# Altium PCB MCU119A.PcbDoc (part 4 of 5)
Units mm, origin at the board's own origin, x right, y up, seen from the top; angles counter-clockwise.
Board outline 58.62 x 144.37 mm, 6 copper layers (Top Signal, GND, Middle Signal, PWR, GND2, Bottom Signal), stack 1.566 mm thick; 316 components, 238 nets, 1210 pads, 1064 vias.
Unrouted connection lines stored in the file: 59.
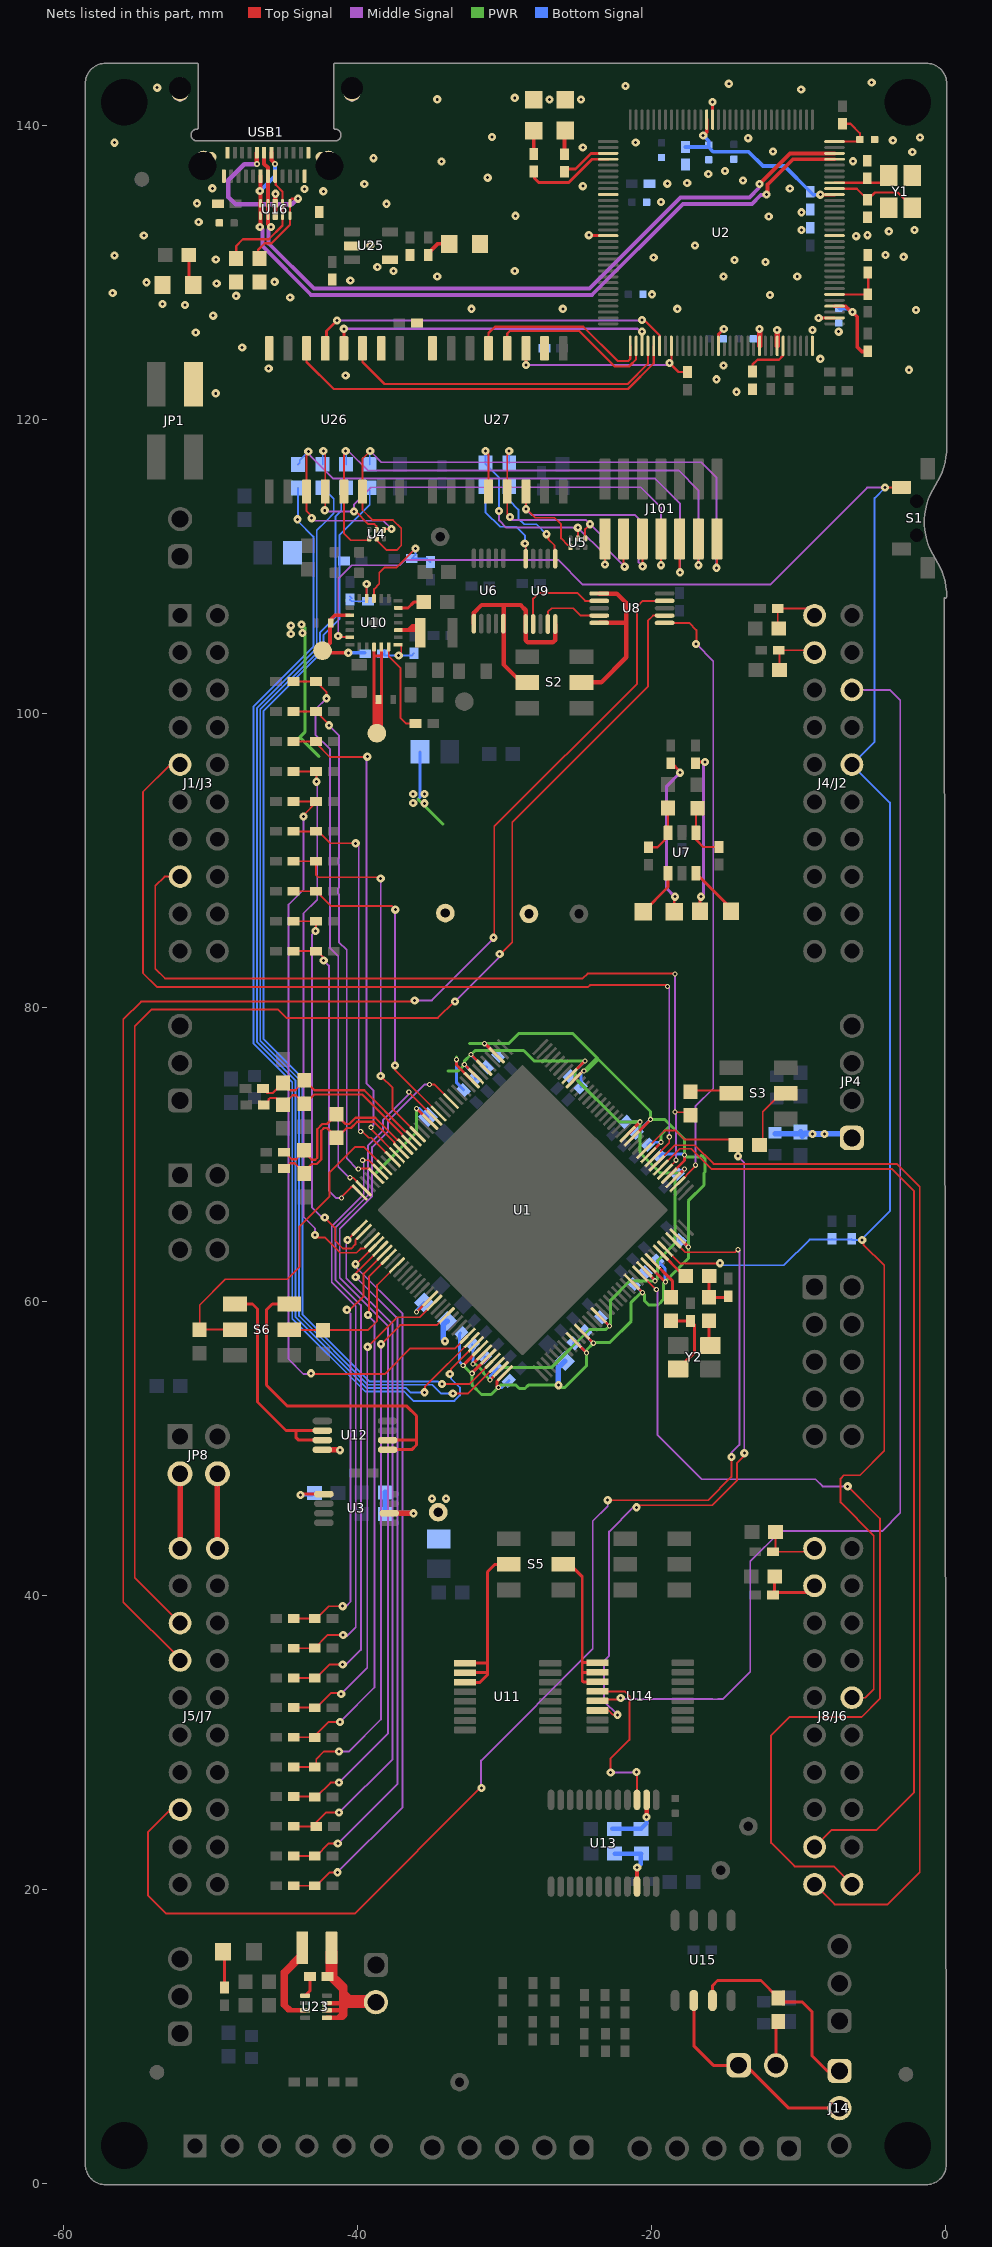
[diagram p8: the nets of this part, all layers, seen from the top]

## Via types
v1: diameter 0.559, hole 0.203, Top Signal to Bottom Signal, tented both sides, 833 vias
v2: diameter 0.5, hole 0.2, Top Signal to Bottom Signal, tented both sides, 146 vias
v3: diameter 0.356, hole 0.203, Top Signal to Bottom Signal, tented both sides, 83 vias
v4: diameter 0.4, hole 0.2, Top Signal to Bottom Signal, tented both sides, 2 vias

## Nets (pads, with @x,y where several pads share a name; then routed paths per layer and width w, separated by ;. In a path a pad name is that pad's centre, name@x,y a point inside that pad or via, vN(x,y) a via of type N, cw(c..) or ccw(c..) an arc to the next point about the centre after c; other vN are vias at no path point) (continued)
GPIO70_BP: J5/J7.44 U8.9 | length 101.4
  Top Signal w0.127: J5/J7.44@-52.061,35.58 -52.061,35.678 -55.931,39.548 -55.931,79.197 -54.712,80.416 -36.17,80.416 v1(-36.093,80.493) ; v1(-30.734,84.76) -30.734,84.942 -30.683,84.993 -30.683,92.329 -20.955,102.057 -20.955,107.29 -20.562,107.683 U8.9@-19.086,107.683
  Middle Signal w0.127: v1(-36.093,80.493) -34.927,80.493 -30.734,84.685 v1(-30.734,84.76)
GPIO70_UARTTX: U8.2 U9.2 | length 6.6
  Top Signal w0.127: U9.2@-28.034,106.106 -28.034,107.145 -28.034,107.831 -27.637,108.228 -25.039,108.228 -24.494,107.683 U8.2@-23.536,107.683
GPIO71: U1.111 U8.6 | length 41.6
  Top Signal w0.127: U8.6@-19.086,106.183 -17.41,106.183 -16.92,105.693 -16.92,104.771 v1(-16.942,104.75) ; U1.111@-18.208,67.989 -16.993,69.204 v3(-16.993,69.28)
  Middle Signal w0.127: v3(-16.993,69.28) -16.993,73.279 -15.773,74.498 -15.773,103.581 v1(-16.942,104.75)
GPIO71_BP: J5/J7.43 U8.7 | length 97.5
  Top Signal w0.127: J5/J7.43@-52.061,38.12 -55.143,41.202 -55.143,78.74 -54,79.883 -45.415,79.883 -44.831,79.299 -34.519,79.299 -33.401,80.416 v1(-33.36,80.416) ; v1(-30.312,83.642) -30.277,83.642 -29.457,84.462 -29.457,92.615 -20.226,101.846 -20.226,106.335 -19.878,106.683 U8.7@-19.086,106.683
  Middle Signal w0.127: v1(-33.36,80.416) -30.312,83.464 v1(-30.312,83.642)
GPIO71_UARTRX: U8.4 U9.4 | length 4.6
  Top Signal w0.127: U9.4@-27.034,106.106 -27.034,106.926 -26.777,107.183 -25.293,107.183 -24.793,106.683 U8.4@-23.536,106.683
GPIO72: J1/J3.8 R31.1 U1.114 | length 58.2
  Top Signal w0.127: J1/J3.8@-52.061,88.92 -53.117,88.92 -53.746,88.29 -53.746,82.652 -53.086,81.991 -24.663,81.991 -24.333,82.321 v3@-18.39,82.321 ; U1.114@-19.056,68.838 -18.313,69.581 v3(-18.313,69.621) ; v3(-18.39,72.907) -18.362,72.88 R31.1@-17.323,72.88
  Middle Signal w0.127: v3(-18.39,82.296) v3(-18.39,72.907) -18.313,72.831 v3(-18.313,69.621)
GPIO76: J8/J6.72 U1.115 | length 68.2
  Top Signal w0.127: U1.115@-19.339,69.121 -18.059,70.401 -17.264,70.401 -15.875,69.012 -3.607,69.012 -2.108,67.513 -2.108,26.594 -4.674,24.028 -7.732,24.028 J8/J6.72@-8.881,22.88
GPIO77: J8/J6.71 U1.116 | length 75
  Top Signal w0.127: U1.116@-19.622,69.403 -18.388,70.637 -17.026,70.637 -15.756,69.367 -3.277,69.367 -1.727,67.818 -1.727,21.158 -3.912,18.974 -7.515,18.974 J8/J6.71@-8.881,20.34 J8/J6.71@-9.072,20.34
GPIO78: J1/J3.5 U1.117 | length 64.1
  Top Signal w0.127: J1/J3.5@-52.061,96.54 -52.736,96.54 -54.585,94.691 -54.585,82.347 -53.645,81.407 -24.285,81.407 -24.158,81.534 -18.999,81.534 v3(-18.898,81.432) ; U1.117@-19.905,69.686 -18.771,70.82 v3(-18.771,71.213)
  Middle Signal w0.127: v3(-18.898,81.432) -18.771,81.305 v3(-18.771,71.213)
GPIO84: R33.2 U1.119 U14.14 | length 54.7
  Top Signal w0.127: U14.14@-23.652,32.172 -22.906,32.172 -22.614,31.879 v1(-22.291,31.879) ; v1(-21.006,45.999) -20.87,46.135 -15.841,46.135 -14.173,47.803 -14.173,48.997 -13.665,49.505 v1(-13.665,49.682) ; U1.119@-20.47,70.252 -19.094,71.628 -18.339,71.628 -17.729,71.018 -14.606,71.018 R33.2@-14.237,70.649 ; v1(-14.097,69.89) R33.2@-14.097,70.333
  Middle Signal w0.127: v1(-22.291,31.879) -23.216,32.804 -23.216,35.535 -22.86,35.89 -22.86,44.348 -21.209,45.999 v1(-21.006,45.999) ; v1(-14.097,69.89) -13.665,69.459 v1(-13.665,49.682)
GPIO84_BP: J4/J2.18 U14.13 | length 89.3
  Top Signal w0.127: U14.13@-23.652,32.822 -23.555,32.918 -22.18,32.918 v1(-22.073,33.025)
  Middle Signal w0.127: v1(-22.073,33.025) -21.991,32.943 -15.831,32.943 -15.827,32.939 -15.465,32.939 -15.461,32.943 -15.119,32.943 -13.259,34.803 -13.259,42.316 -11.201,44.374 -4.293,44.374 -3.048,45.618 -3.048,100.914 -3.754,101.62 J4/J2.18@-6.341,101.62
GPIO84_Q1A: U13.3 U14.12 | length 11.7
  Top Signal w0.127: U14.12@-23.652,33.472 -21.813,33.472 -21.488,33.147 -21.488,30.175 -22.758,28.905 v1(-22.758,27.96) ; U13.3@-20.966,26.089 v1@-20.966,27.991
  Middle Signal w0.127: v1(-22.758,27.96) -21.037,27.96 v1(-21.006,27.991)
GPIO103: J5/J7.48 U1.105 | length 86.6
  Top Signal w0.127: J5/J7.48@-52.061,25.42 -52.722,25.42 -54.254,23.887 -54.254,19.583 -53.035,18.364 -40.154,18.364 -31.619,26.899 v1(-31.547,26.899) ; v1(-22.962,46.482) -16.124,46.482 -14.541,48.065 v1(-14.541,49.428) ; U1.105@-18.49,64.171 -17.675,63.355 -14.273,63.355 v3(-14.097,63.531)
  Middle Signal w0.127: v1@-31.572,26.899 -31.572,28.766 -23.978,36.36 -23.978,45.067 -22.962,46.083 v1(-22.962,46.482) ; v1(-14.541,49.428) -14.541,49.695 -13.995,50.241 -13.995,63.429 v3(-14.097,63.531)
GPIO127: J8/J6.51 U1.97 | length 63.6
  Top Signal w0.127: U1.97@-20.753,61.908 -19.656,60.811 v3(-19.65,60.811) ; v1(-6.629,47.426) -4.441,45.237 -4.441,32.973 -5.69,31.725 -10.592,31.725 -11.836,30.48 -11.836,23.165 -10.236,21.565 -7.566,21.565 J8/J6.51@-6.341,20.34
  Middle Signal w0.127: v3(-19.65,60.811) -19.583,60.744 -19.583,50.927 -16.561,47.904 -8.819,47.904 -8.341,47.426 v1(-6.629,47.426)
GPIO220_X1: R21.1 U1.102 | length 2.4
  Top Signal w0.203: U1.102@-19.339,63.322 -17.866,61.849 R21.1@-17.539,61.849
GPIO221_X2: R20.1 U1.100 | length 3.1
  Top Signal w0.203: U1.100@-19.905,62.757 -18.561,61.413 -18.561,60.395 R20.1@-18.665,60.291 ; R20.1@-18.491,60.515 R20.1@-18.455,60.479
MCU_A0/DACA_OUT: C39.1 R37.2 U1.36 | length 21
  Top Signal w0.127: R37.2@-44.334,83.844 -42.927,83.844 C39.1@-42.806,83.844 -42.738,83.844 -42.285,83.391 v1(-42.285,83.21) ; v3(-41.072,67.038) -41.072,67.138 -40.422,67.788 -40.254,67.788 -39.89,67.424 U1.36@-39.845,67.424
  Middle Signal w0.127: v1(-42.285,83.21) -41.935,82.86 -41.935,67.551 -41.422,67.038 v3(-41.072,67.038)
MCU_A1: C26.1 R38.2 U1.35 | length 38.1
  Top Signal w0.127: R38.2@-44.334,102.191 C26.1@-42.806,102.191 -42.088,101.473 v1(-42.088,101.051) ; v3(-40.493,68.428) -40.284,68.428 U1.35@-39.562,67.706
  Middle Signal w0.127: v1(-42.088,101.051) -42.85,100.289 -42.85,98.577 -41.848,97.576 -41.848,84.866 -41.848,84.504 -41.848,84.051 -41.783,83.985 -41.783,83.976 -41.295,83.489 -41.295,69.179 -40.544,68.428 v3(-40.493,68.428)
MCU_A2: C40.1 R39.2 U1.28 | length 27.3
  Top Signal w0.127: R39.2@-44.334,91.998 C40.1@-42.806,91.998 -42.745,91.938 -42.679,91.872 -42.536,91.872 -41.85,91.186 v1(-40.112,91.186) ; v3(-39.767,71.577) -39.726,71.594 ccw(c-39.646,71.675) -39.646,71.561 -39.234,71.149 -39.048,71.149 U1.28@-37.585,69.686
  Middle Signal w0.127: v1(-40.112,91.186) -39.903,90.978 -39.903,71.907 -39.903,71.713 v3(-39.767,71.577)
MCU_A3: C27.1 R40.2 U1.27 | length 33.7
  Top Signal w0.127: R40.2@-44.334,98.114 C27.1@-42.806,98.114 -42.806,98 -41.859,97.053 -39.345,97.053 v1(-39.319,97.079) ; v3(-39.065,71.857) -39.065,71.735 U1.27@-37.3,69.969
  Middle Signal w0.127: v1(-39.319,97.079) -39.37,97.028 -39.37,74.828 -38.887,74.346 -38.887,72.034 v3(-39.065,71.857)
MCU_A4A5_N: C24.1 C29.2 R42.2 U1.23 | length 12.8
  Top Signal w0.152: R42.2@-46.415,74.495 -46.114,74.193 -45.745,74.193 -45.072,74.867 C29.2@-45.069,74.867 -44.574,74.371 -44.221,74.371 -43.612,74.981 C24.1@-43.612,75.07 -43.567,75.025 -42.913,74.371 -39.522,74.371 -36.728,71.577 -36.645,71.577 U1.23@-36.168,71.1
MCU_A4A5_P: C24.2 C41.2 R41.2 U1.24 | length 12.5
  Top Signal w0.152: R41.2@-46.365,73.368 -46.025,73.708 -46.025,73.762 -45.928,73.858 -45.55,73.858 -45.06,73.368 -44.386,74.041 -44.183,74.041 C24.2@-43.612,73.47 -43.548,73.47 -42.926,74.092 -39.656,74.092 -36.957,71.393 -36.957,71.324 U1.24@-36.451,70.818
MCU_A6: C42.1 R43.2 U1.18 | length 48.6
  Top Signal w0.127: R43.2@-44.323,34.389 -44.318,34.384 -42.795,34.384 -41.872,35.306 v1(-40.996,35.306) ; v3(-36.497,74.261) -36.497,74.257 U1.18@-34.754,72.515
  Middle Signal w0.127: v1(-40.996,35.306) -40.742,35.306 -39.751,36.297 -39.751,59.757 -41.49,61.496 -41.49,65.007 -39.279,67.217 -39.279,70.597 -38.259,71.618 -38.259,72.342 -36.497,74.104 v3(-36.497,74.261)
MCU_A7: C30.1 R45.2 U1.17 | length 22.5
  Top Signal w0.127: R45.2@-44.334,87.921 C30.1@-42.806,87.921 -41.803,86.919 -37.668,86.919 v1(-37.414,86.665) ; v1(-37.44,76.073) -37.44,75.766 U1.17@-34.471,72.798
  Middle Signal w0.127: v1(-37.44,76.073) -37.44,86.639 v1(-37.414,86.665)
MCU_A14/B14/C14: C43.1 R46.2 U1.32 | length 35.4
  Top Signal w0.127: R46.2@-44.334,100.152 C43.1@-42.806,100.152 -41.935,99.282 v1(-41.935,99.212) ; v3(-39.929,69.012) -39.878,69.063 -39.221,69.063 U1.32@-38.714,68.555
  Middle Signal w0.127: v1(-41.935,99.212) -41.25,98.527 -41.25,90.184 -41.286,90.148 -41.286,89.786 -41.25,89.749 -41.25,88.172 -41.305,88.116 -41.305,87.754 -41.25,87.698 -41.25,84.464 -40.716,83.931 -40.716,69.736 -39.992,69.012 v3(-39.929,69.012)
MCU_A15/B15/C15: C31.1 R47.2 U1.31 | length 39.7
  Top Signal w0.127: R47.2@-44.323,36.41 C31.1@-42.937,36.41 ; C31.1@-42.891,36.424 -42.002,37.313 v1(-40.957,37.313) ; v3(-39.637,69.616) -39.209,69.616 U1.31@-38.431,68.838
  Middle Signal w0.127: v1(-40.957,37.313) -40.881,37.236 -40.716,37.236 -40.107,37.846 -40.107,59.665 -41.741,61.299 -41.741,65.117 -39.562,67.296 -39.562,69.541 v3(-39.637,69.616)
MCU_B2B3_N: C25.1 C32.2 R49.2 U1.25 | length 12.7
  Top Signal w0.152: R49.2@-44.993,70.155 -44.936,70.155 -44.468,69.686 -44.157,69.686 -43.637,70.206 C32.2@-43.637,70.295 ; C32.2@-43.637,70.18 -43.104,69.647 -42.87,69.647 -42.731,69.785 -42.731,71.734 -42.38,72.085 -42.066,72.085 C25.1@-41.402,72.749 -41.402,72.683 -40.805,72.085 -40.553,72.085 -40.126,72.511 -38.771,72.511 -37.278,71.018 -37.217,71.018 U1.25@-36.734,70.535
MCU_B2B3_P: C25.2 C44.2 R48.2 U1.26 | length 12.5
  Top Signal w0.152: R48.2@-44.993,69.063 -44.907,69.063 -44.566,69.403 -44.257,69.403 C44.2@-43.612,68.758 ; C44.2@-43.612,68.718 C44.2@-43.612,68.758 ; U1.26@-37.017,70.252 -37.49,70.726 -37.49,70.835 -38.887,72.232 -40.011,72.232 -40.437,71.806 -40.727,71.806 -41.384,71.149 C25.2@-41.402,71.149 -42.059,71.806 -42.264,71.806 -42.452,71.618 -42.452,69.67 -42.754,69.367 -43.093,69.367 -43.612,68.849 C44.2@-43.612,68.758
MCU_B9: C33.1 R51.2 U1.14 | length 58.4
  Top Signal w0.127: R51.2@-44.323,26.308 -42.812,26.308 -42.795,26.291 -41.816,27.27 v1(-41.25,27.27) ; v3(-35.088,74.778) -34.754,74.778 U1.14@-33.623,73.646
  Middle Signal w0.127: v1(-41.25,27.27) -37.922,30.597 -37.922,58.356 -41.199,61.633 -41.199,64.965 -38.989,67.174 -38.989,70.51 -37.904,71.595 -37.904,72.288 -35.414,74.778 v3(-35.088,74.778)
MCU_C0: C46.1 R52.2 U1.37 | length 46.6
  Top Signal w0.127: R52.2@-44.323,24.288 -42.814,24.288 C46.1@-42.795,24.268 -42.795,24.573 -42.146,25.222 v1(-41.25,25.222) ; v1(-40.665,64.186) -40.665,64.199 U1.37@-39.845,65.019
  Middle Signal w0.127: v1(-41.25,25.222) -37.603,28.869 -37.603,58.448 -40.751,61.596 -40.751,64.1 v1(-40.665,64.186)
MCU_C1: C34.1 R53.2 U1.38 | length 27
  Top Signal w0.127: R53.2@-44.334,85.883 C34.1@-42.806,85.883 -42.806,85.261 v1(-42.85,85.217) ; v1(-42.216,65.714) -41.504,65.002 -41.504,64.135 -40.974,63.605 -40.408,63.605 -40.128,63.885 -40.128,64.171 U1.38@-39.562,64.737
  Middle Signal w0.127: v1(-42.85,85.217) -43.08,84.987 -43.08,66.397 -42.316,65.634 -42.297,65.634 v1(-42.216,65.714)
MCU_C2: C47.1 R54.2 U1.43 | length 29.4
  Top Signal w0.127: R54.2@-44.323,38.43 -42.795,38.43 -41.956,39.268 v1(-40.996,39.268) ; v1(-40.716,59.436) -40.503,59.436 -39.573,60.365 -39.573,61.897 U1.43@-38.148,63.322
  Middle Signal w0.127: v1(-40.996,39.268) -40.767,39.268 -40.462,39.573 -40.462,59.182 v1(-40.716,59.436)
MCU_C3: C35.1 R55.2 U1.44 | length 37.1
  Top Signal w0.127: R55.2@-44.323,30.349 C35.1@-42.891,30.349 ; C35.1@-42.85,30.328 C35.1@-42.891,30.328 -42.891,30.439 -41.935,31.394 v1(-41.173,31.394) ; v1(-39.279,59.08) -39.209,59.15 -39.209,61.696 U1.44@-37.865,63.039
  Middle Signal w0.127: v1(-41.173,31.394) -38.832,33.736 -38.832,58.632 v1(-39.279,59.08)
MCU_C8: C48.1 R56.2 U1.58 | length 38.4
  Top Signal w0.127: R56.2@-44.323,28.329 -42.809,28.329 -42.795,28.314 -42.795,28.859 -42.266,29.388 v1(-41.25,29.388) ; v1(-38.379,57.099) -37.084,58.395 -34.59,58.395 U1.58@-33.905,59.08
  Middle Signal w0.127: v1(-41.25,29.388) -40.564,29.388 -38.395,31.557 v1@-38.395,57.023
MCU_D1: C36.1 R57.2 U1.40 | length 38.6
  Top Signal w0.127: R57.2@-44.334,96.075 C36.1@-42.806,96.075 -42.901,95.98 -42.901,95.913 -42.774,95.786 v1(-42.774,95.377) ; v1(-42.88,64.524) -42.724,64.369 -42.201,64.369 -41.946,64.113 -41.946,64.105 -41.163,63.322 -40.056,63.322 -39.773,63.605 -39.562,63.605 U1.40@-38.997,64.171
  Middle Signal w0.127: v1(-42.88,64.524) -42.88,64.978 -43.663,65.761 -43.663,86.411 -42.723,87.351 -42.723,95.326 v1(-42.774,95.377)
MCU_D5: C49.1 R58.2 U1.55 | length 33.8
  Top Signal w0.127: R58.2@-44.323,32.369 -42.803,32.369 -42.795,32.361 -41.805,33.35 -41.148,33.35 v1(-41.097,33.299) ; v1(-39.294,56.921) -37.287,58.928 -35.754,58.928 U1.55@-34.754,59.928
  Middle Signal w0.127: v1(-41.097,33.299) -39.319,35.077 -39.319,56.896 v1(-39.294,56.921)
MCU_E0/DACB_OUT: C37.1 R60.2 U1.41 | length 49.9
  Top Signal w0.127: R60.2@-44.323,20.247 -42.793,20.247 -42.789,20.244 -41.875,21.158 v1(-41.351,21.158) ; v1(-40.128,62.54) -40.061,62.54 -39.352,63.25 U1.41@-38.714,63.888
  Middle Signal w0.127: v1(-41.351,21.158) -36.919,25.59 -36.919,59.122 -36.919,59.176 -40.128,62.385 v1(-40.128,62.54)
MCU_E1: C50.1 R61.2 U1.42 | length 47.4
  Top Signal w0.127: R61.2@-44.323,22.268 -42.797,22.268 -41.939,23.126 -41.338,23.126 v1(-41.326,23.114) ; v1(-40.107,61.671) -40.107,61.929 -39.4,62.636 U1.42@-38.431,63.605
  Middle Signal w0.127: v1(-41.326,23.114) -37.262,27.178 -37.262,58.826 v1(-40.107,61.671) v1@-40.112,61.666
MCU_E7: C38.1 R62.2 U1.63 | length 54
  Top Signal w0.127: R62.2@-44.334,94.037 C38.1@-42.806,94.037 -42.806,93.963 -43.663,93.106 v1(-43.663,93.015) ; v1(-43.155,55.118) -43.104,55.067 -38.148,55.067 -36.42,56.794 -33.362,56.794 U1.63@-32.491,57.665
  Middle Signal w0.127: v1(-43.663,93.015) -43.663,88.036 -44.679,87.02 -44.679,56.083 -43.663,55.067 -43.205,55.067 v1(-43.155,55.118)
MCU_RXD: R165.1 U9.6 | length 6.6
  Top Signal w0.127: v1@-27,112.217 -27,111.878 -26.581,111.458 -26.581,110.603 U9.6@-26.534,110.556
  Bottom Signal w0.127: R165.1@-29.661,115.466 -29.661,114.522 -29.033,113.894 -29.033,113.285 -28.644,112.896 -27.806,112.896 v1(-27.127,112.217)
MCU_RXD_INT: J101.12 R165.2 U5.4 U27.13 | length 18
  Top Signal w0.127: v1(-29.661,117.881) -29.799,117.743 U27.13@-29.799,115.118 -29.799,113.568 v1(-29.616,113.386) ; U5.4@-24.494,111.933 -24.494,112.565 v1(-24.155,112.903) ; J101.12@-21.874,111.903 -21.874,110.078 v1(-21.803,110.007)
  Middle Signal w0.127: v1(-29.616,113.386) -29.413,113.182 -24.435,113.182 v1(-24.155,112.903) -23.444,112.192 -23.444,111.648 v1(-21.803,110.007)
  Bottom Signal w0.127: R165.2@-29.661,117.066 v1(-29.661,117.881)
MCU_TCK: R98.1 U1.70 | length 76.3
  Top Signal w0.127: v1(-33.503,53.746) -32.45,53.746 U1.70@-30.511,55.686
  Bottom Signal w0.127: R98.1@-40.755,115.371 -41.097,115.028 -41.097,113.825 -41.478,113.444 -41.478,106.598 -42.533,105.543 -42.533,104.369 -46.609,100.293 -46.609,77.761 -43.967,75.119 -43.967,59.028 -39.274,54.335 -34.912,54.335 -34.323,53.746 v1(-33.503,53.746)
MCU_TCK_INT: J101.4 R98.2 U4.1 U26.13 | length 40.5
  Top Signal w0.127: v1(-40.792,117.881) -40.916,117.757 U26.13@-40.916,115.118 -40.916,112.29 -40.437,111.811 U4.1@-39.193,111.811 ; J101.4@-16.794,111.903 -16.794,110.114 v1(-16.789,110.109)
  Middle Signal w0.127: v1(-40.792,117.881) -40.615,117.881 -39.294,116.561 -18.136,116.561 -16.789,115.214 v1(-16.789,110.109)
  Bottom Signal w0.127: v1(-40.792,117.881) -40.755,117.844 R98.2@-40.755,116.971
MCU_TDI: R99.1 U1.64 | length 75.8
  Top Signal w0.127: v1(-35.435,53.823) -35.397,53.861 -35.397,54.194 U1.64@-32.208,57.383
  Bottom Signal w0.127: R99.1@-42.355,115.371 -41.605,114.621 -41.605,113.64 -42.129,113.116 ; -42.129,113.115 -42.762,112.483 -42.762,104.463 -46.838,100.388 -46.838,77.666 -44.196,75.025 -44.196,58.933 -39.369,54.106 -36.68,54.106 -36.396,53.823 v1(-35.435,53.823)
MCU_TDI_INT: J101.8 R99.2 U4.5 U26.12 | length 37.4
  Top Signal w0.127: v1(-42.315,117.881) -42.186,117.752 U26.12@-42.186,115.118 -42.186,113.873 v1(-42.216,113.843) ; v1(-40.234,113.767) -40.107,113.767 -39.243,112.903 -38.84,112.903 -38.684,112.747 U4.5@-38.684,112.517 ; v1(-19.339,110.109) -19.334,110.114 J101.8@-19.334,111.903
  Middle Signal w0.127: v1(-42.216,113.843) -42.14,113.767 v1(-40.234,113.767) -40.234,114.224 -39.04,115.418 -20.717,115.418 -19.339,114.039 v1(-19.339,110.109)
  Bottom Signal w0.127: R99.2@-42.355,116.971 -42.355,117.841 v1(-42.315,117.881)
MCU_TDO: R100.1 U1.65 | length 78.2
  Top Signal w0.127: v1(-33.706,55.067) -33.627,55.146 -33.627,55.399 U1.65@-31.926,57.1
  Bottom Signal w0.127: R100.1@-44.039,115.358 -44.039,113.263 v1(-44.069,113.233) -44.069,113.132 -42.991,112.053 -42.991,104.558 -47.066,100.482 -47.066,77.572 -44.425,74.93 -44.425,58.839 -39.464,53.878 -36.814,53.878 -36.505,53.569 -36.505,53.565 -36.178,53.238 -33.393,53.238 -33.018,53.613 -33.018,54.15 -33.623,54.756 -33.623,54.985 v1(-33.706,55.067)
MCU_TDO_INT: J101.6 R100.2 U4.4 U26.11 | length 45.9
  Top Signal w0.127: v1(-43.332,117.841) -43.456,117.718 U26.11@-43.456,115.118 -43.456,113.789 -43.104,113.436 v1(-43.104,113.309) ; U4.4@-38.122,112.573 v1(-37.668,112.573) ; J101.6@-18.064,111.903 -18.064,109.656 v1(-18.034,109.626)
  Middle Signal w0.127: v1(-43.332,117.841) -43.332,117.678 -41.665,116.011 -19.745,116.011 -18.034,114.3 v1(-18.034,109.626) ; v1(-43.104,113.309) -42.926,113.132 -38.227,113.132 v1(-37.668,112.573)
  Bottom Signal w0.127: R100.2@-44.039,116.958 -43.917,117.08 -43.917,117.257 v1(-43.332,117.841)
MCU_TMS: R44.1 R97.1 U1.69 | length 75.9
  Top Signal w0.127: v1(-34.239,54.381) -32.381,54.381 U1.69@-30.794,55.968
  Bottom Signal w0.127: R97.1@-39.155,115.371 -39.155,114.217 -41.215,112.157 -41.215,106.436 -42.305,105.345 -42.305,104.274 -46.38,100.198 -46.38,77.856 -43.739,75.214 -43.739,59.123 -39.18,54.564 -34.529,54.564 -34.347,54.381 v1(-34.239,54.381)
MCU_TMS_INT: J101.2 R97.2 U4.2 U26.14 | length 44
  Top Signal w0.127: v1(-39.123,117.881) -39.646,117.359 U26.14@-39.646,115.118 -39.646,113.865 -38.964,113.182 -37.571,113.182 -37.008,112.619 -37.008,111.449 -37.317,111.14 -37.991,111.14 U4.2@-38.669,111.817 ; v1(-15.561,109.929) -15.524,109.966 J101.2@-15.524,111.903
  Middle Signal w0.127: v1(-39.123,117.881) -38.361,117.119 -16.586,117.119 -15.561,116.094 v1(-15.561,109.929)
  Bottom Signal w0.127: R97.2@-39.155,116.971 -39.155,117.85 v1(-39.123,117.881)
MCU_TXD: R171.1 U9.10 | length 6.7
  Top Signal w0.127: v1(-28.6,111.582) -28.534,111.515 U9.10@-28.534,110.556
  Bottom Signal w0.127: R171.1@-31.279,115.466 -31.279,113.728 -30.277,112.725 -29.185,112.725 -28.6,112.141 v1(-28.6,111.582)
MCU_TXD_INT: J101.14 R171.2 U5.5 U27.12 | length 19.3
  Top Signal w0.127: v1(-31.279,117.881) -31.069,117.671 U27.12@-31.069,115.118 ; U5.5@-24.994,111.933 v1(-24.994,112.665) ; J101.14@-23.144,111.903 -23.144,110.164 v1(-23.139,110.16)
  Middle Signal w0.127: v1(-30.353,113.792) -30.353,113.157 -29.861,112.665 v1(-24.994,112.665) -23.139,110.811 v1(-23.139,110.16)
  Bottom Signal w0.127: v1(-31.279,117.881) R171.2@-31.279,117.066 -31.279,117.001 -30.353,116.075 v1(-30.353,113.792)
NetC1_1: C1.1 J4/J2.39 R2.1 | length 3.9
  Top Signal w0.127: R2.1@-11.265,102.972 -11.265,104.27 C1.1@-11.313,104.318 -9.039,104.318 J4/J2.39@-8.881,104.16
NetC2_1: C2.1 J4/J2.40 R1.1 | length 4.1
  Top Signal w0.127: R1.1@-11.316,105.791 -11.389,105.864 C2.1@-11.389,107.163 -9.344,107.163 J4/J2.40@-8.881,106.7
NetC3_1: C3.1 J8/J6.80 R3.1 | length 4.3
  Top Signal w0.127: R3.1@-11.544,44.323 -11.544,43.151 C3.1@-11.719,42.977 -9.104,42.977 J8/J6.80@-8.881,43.2
NetC4_1: C4.1 J8/J6.79 R4.1 | length 4.4
  Top Signal w0.2: R4.1@-11.621,41.58 -11.621,40.307 -11.719,40.208 -9.333,40.208 J8/J6.79@-8.881,40.66
NetC45_1: C45.1 R50.2 U1.22 | length 25.4
  Top Signal w0.127: R50.2@-44.334,89.96 C45.1@-42.806,89.96 -42.806,89.008 -42.672,88.875 -38.485,88.875 v1(-38.409,88.798) ; v1(-38.409,75.343) -37.603,74.538 -37.603,73.101 U1.22@-35.885,71.383
  Middle Signal w0.127: v1(-38.409,75.343) v1(-38.409,88.798)
NetC52_1: C52.1 U3.5 | length 2.6
  Top Signal w0.203: v1(-43.866,46.838) -43.815,46.888 U3.5@-42.288,46.888
  Bottom Signal w0.203: v1(-43.866,46.838) -43.04,46.838 C52.1@-42.913,46.965
NetC107_1: C107.1 U10.18 | length 1.9
  Top Signal w0.203: U10.18@-37.212,107.197 -36.554,107.197 -36.157,107.594 C107.1@-35.471,107.594
NetC131_2: C131.2 R164.2 U2.96 | length 3.7
  Top Signal w0.152: U2.96@-7.526,138.935 -5.946,138.935 C131.2@-5.799,139.081 -5.799,139.508 -6.436,140.145 R164.2@-6.986,140.145
NetC142_1: C142.1 C143.2 C144.1 U2.87 U2.115 | length 13.5
  Top Signal w0.254: v1(-16.465,139.354) -16.226,139.593 U2.115@-16.226,140.435 ; v1(-8.493,135.32) U2.87@-7.511,135.32
  Bottom Signal w0.254: C144.1@-17.661,138.572 C143.2@-16.217,138.572 ; v1(-16.465,139.354) -16.087,138.976 C143.2@-16.087,138.702 -16.087,138.545 -15.786,138.244 -13.37,138.244 -12.402,137.276 -10.933,137.276 C142.1@-9.173,135.516 -8.977,135.32 v1(-8.493,135.32)
NetC145_2: C145.2 R177.1 U2.68 | length 5.8
  Top Signal w0.254: U2.68@-7.526,127.735 -6.779,127.735 -6.379,127.335 v1(-6.296,127.335) -5.982,127.02 -5.982,124.963 -5.676,124.657 R177.1@-5.232,124.657
  Bottom Signal w0.254: C145.2@-7.242,127.648 -7.159,127.565 -6.609,127.565 -6.379,127.335 v1(-6.296,127.335)
NetC146_1: C146.1 U2.89 Y1.3 | length 3.9
  Top Signal w0.152: U2.89@-7.526,136.135 -4.328,136.135 Y1.3@-3.834,136.629
NetC147_1: C147.1 U2.88 Y1.1 | length 6.3
  Top Signal w0.152: U2.88@-7.526,135.735 -6.007,135.735 -5.223,134.951 -5.223,135.023 -4.77,135.476 -3.227,135.476 -2.234,134.482 Y1.1@-2.234,134.429
NetJ5/J7_41: J5/J7.41 JP8.3 | length 5.1
  Top Signal w0.381: J5/J7.41@-52.061,43.2 JP8.3@-52.061,48.28
NetJ5/J7_61: J5/J7.61 JP8.4 | length 5.1
  Top Signal w0.381: J5/J7.61@-49.521,43.2 JP8.4@-49.521,48.28
NetJ14_1: J14.1 R11.2 U15.7 | length 14.3
  Top Signal w0.203: U15.7@-15.831,12.439 -15.831,13.445 -15.484,13.792 -12.535,13.792 R11.2@-11.354,12.611 -11.062,12.319 -9.703,12.319 -9.072,11.688 -9.072,8.691 -8.026,7.645 J14.1@-7.188,7.645 J14.1@-6.934,7.645
NetJ14_2: J14.2 JP9.1 U15.6 | length 15
  Top Signal w0.203: U15.6@-17.101,12.439 -17.101,9.354 -15.773,8.026 JP9.1@-14.046,8.026 -13.564,8.026 -10.643,5.105 J14.2@-7.188,5.105 -7.137,5.055 J14.2@-6.979,5.055
NetJ17_2: J17.2 L4.1 R107.2 U23.1 U23.2 U23.3 | length 28
  Top Signal w0.305: U23.1@-42.072,11.264 -41.326,11.264 ; U23.2@-42.072,11.764 -41.097,11.764 ; U23.3@-42.072,12.264 -41.097,12.264 ; L4.1@-41.748,16.027 -41.748,14.062 R107.2@-41.631,13.945 ; L4.1@-41.748,16.027 -41.504,15.783 -41.504,14.072 R107.2@-41.631,13.945 ; L4.1@-41.748,16.027 -42.012,15.764 -42.012,14.656 -42.021,14.646 R107.2@-42.021,14.072 -41.097,13.148 ; R107.2@-41.631,13.945 -41.097,13.411 -41.097,13.148 ; R107.2@-41.631,13.945 -41.359,13.945 -40.818,13.403 -40.818,12.954 ; -41.326,11.264 -40.984,11.264 -40.818,11.43 -40.818,11.938 ; -41.326,11.264 -41.097,11.493 -41.097,11.764 ; -41.097,11.764 -41.097,12.264 ; -41.097,12.264 -41.097,13.148 ; -41.097,12.264 -40.818,12.264 ; -40.818,11.938 -40.665,12.09 ; -40.818,11.938 -40.818,12.264 ; -40.818,12.264 -40.492,12.264 ; -40.818,12.264 -40.818,12.421 ; -40.818,12.421 -40.818,12.575 ; -40.818,12.421 J17.2@-38.837,12.421 ; -40.818,12.575 -40.513,12.575 ; -40.818,12.575 -40.818,12.954 ; -40.818,12.954 -40.513,12.649 ; -40.665,12.09 -40.492,12.264 ; -40.665,12.09 -38.964,12.09 J17.2@-38.79,12.264 ; -40.513,12.575 J17.2@-38.991,12.575 ; -40.513,12.575 -40.513,12.649 ; -40.513,12.649 -39.065,12.649 J17.2@-38.991,12.575 ; -40.492,12.264 J17.2@-38.79,12.264 ; J17.2@-38.991,12.575 J17.2@-38.837,12.421 ; J17.2@-38.837,12.421 J17.2@-38.735,12.319 J17.2@-38.79,12.264
NetJP9_2: JP9.2 R11.1 | length 3
  Top Signal w0.203: JP9.2@-11.506,8.026 -11.506,10.859 R11.1@-11.354,11.011
NetL4_2: L4.2 U23.7 | length 10.6
  Top Signal w0.305: L4.2@-43.748,16.027 L4.2@-43.748,15.545 ; U23.7@-43.552,11.764 -44.505,11.764 ; -44.505,11.764 -44.721,11.764 -45.085,12.129 -45.085,14.376 -43.917,15.545 L4.2@-43.748,15.545 ; -44.505,11.764 -44.882,12.141 -44.882,14.224 -43.748,15.358 L4.2@-43.748,15.545
NetL5_1: L5.1 U10.15 | length 2.7
  Top Signal w0.254: U10.15@-37.212,105.697 -36.517,105.697 ; L5.1@-35.72,105.512 L5.1@-35.906,105.697 ; -36.517,105.697 -36.316,105.898 ; -36.517,105.697 L5.1@-35.906,105.697 ; -36.316,105.898 -36.246,105.969 -36.093,105.969 -36.093,105.885 ; -36.316,105.898 -36.107,105.898 -36.093,105.885 ; -36.093,105.885 L5.1@-35.906,105.697
NetLED1_2: LED1.2 R69.1 | length 2.2
  Top Signal w0.203: R69.1@-51.461,131.233 -51.461,129.482 LED1.2@-51.161,129.182
NetLED3_2: LED3.2 R82.1 | length 2.5
  Top Signal w0.203: LED3.2@-49.132,15.748 -49.042,15.658 R82.1@-49.042,13.32
NetLED4_1: LED4.1 U7.6 | length 3.6
  Top Signal w0.203: U7.6@-16.955,89.15 -14.571,86.766 LED4.1@-14.571,86.563
NetLED4_2: LED4.2 R12.1 | length 10.9
  Top Signal w0.203: R12.1@-16.942,96.695 -16.913,96.723 v1(-16.332,96.723) ; LED4.2@-16.671,86.563 -16.671,87.494 v1(-16.612,87.554)
  Middle Signal w0.203: v1(-16.612,87.554) -16.434,87.732 -16.434,96.622 v1(-16.332,96.723)
NetLED5_1: LED5.1 R13.1 | length 11.1
  Top Signal w0.203: R13.1@-18.669,96.698 -18.034,96.063 v1(-18.034,95.987) ; LED5.1@-18.432,86.533 -18.432,87.512 v1(-18.39,87.554)
  Middle Signal w0.203: v1(-18.39,87.554) -18.948,88.113 -18.948,95.072 v1(-18.034,95.987)
NetLED5_2: LED5.2 U7.4 | length 3.3
  Top Signal w0.203: LED5.2@-20.532,86.533 -18.855,88.209 U7.4@-18.855,89.15
NetLED7_2: LED7.2 R96.2 | length 1.7
  Top Signal w0.254: R96.2@-35.292,131.215 -34.515,131.992 LED7.2@-33.866,131.992
NetLED8_1: LED8.1 R172.1 | length 1.6
  Top Signal w0.254: R172.1@-25.892,138.078 -25.892,139.645 LED8.1@-25.842,139.695
NetLED9_1: LED9.1 R173.1 | length 1.7
  Top Signal w0.254: R173.1@-27.994,138.098 -27.994,139.673 LED9.1@-27.982,139.686 LED9.1@-27.889,139.593
NetR14_1: R14.1 R17.2 U7.1 | length 3.9
  Top Signal w0.152: R17.2@-16.993,93.536 -16.955,93.498 U7.1@-16.955,91.9 -16.955,91.444 -16.449,90.939 R14.1@-15.376,90.939
NetR15_1: R15.1 R19.2 U7.3 | length 3.6
  Top Signal w0.152: R15.1@-20.193,90.922 -19.568,90.922 -18.855,91.635 U7.3@-18.855,91.9 -18.855,93.337 R19.2@-18.669,93.523
NetR18_1: R18.1 R26.1 U10.13 | length 3.5
  Top Signal w0.127: U10.13@-37.224,104.697 -37.108,104.697 -37.008,104.597 -37.008,104.111 -37.157,103.962 v1(-37.186,103.962)
  Bottom Signal w0.127: R18.1@-38.262,104.084 R18.1@-38.16,103.982 ; R18.1@-38.16,104.292 R18.1@-38.16,103.982 ; R26.1@-36.15,104.121 -36.31,103.962 v1(-37.186,103.962) -38.141,103.962 R18.1@-38.16,103.982
NetR22_1: R22.1 Y2.3 | length 1.7
  Top Signal w0.203: R22.1@-16.053,58.691 -16.053,57.094 Y2.3@-15.969,57.01
NetR25_1: R25.1 R32.2 U10.22 | length 7.2
  Top Signal w0.127: U10.22@-38.862,107.847 -38.862,108.482 -38.503,108.841 -38.503,109.588 -38.135,109.957 -37.328,109.957 v1(-36.043,111.242)
  Bottom Signal w0.127: v1(-36.043,111.242) -36.043,110.814 R32.2@-36.291,110.566 -35.267,110.566 R25.1@-35.027,110.326
NetR28_1: R28.1 R29.2 U10.23 | length 3.7
  Top Signal w0.127: U10.23@-39.362,107.847 v1(-39.362,108.839)
  Bottom Signal w0.127: R28.1@-40.499,107.77 -40.39,107.66 R29.2@-39.276,107.66 -39.362,107.745 v1(-39.362,108.839) ; R28.1@-40.499,107.985 R28.1@-40.373,107.859
NetR30_1: R30.1 R35.2 U13.2 | length 4.1
  Top Signal w0.305: v1(-20.32,24.917) -20.316,24.921 U13.2@-20.316,26.089
  Bottom Signal w0.305: R30.1@-22.644,24.119 R35.2@-20.688,24.119 -20.32,24.488 v1(-20.32,24.917)
NetR31_2: R31.2 S3.5 | length 3.5
  Top Signal w0.127: R31.2@-17.323,74.48 -17.214,74.371 -14.956,74.371 -14.55,73.965 S3.5@-14.046,73.965
NetR33_1: R33.1 S3.2 | length 4.4
  Top Signal w0.127: R33.1@-12.637,70.649 -12.412,70.875 -12.412,72.907 -11.587,73.731 -11.083,73.731 S3.2@-10.85,73.965
NetR34_1: R34.1 R36.1 U13.22 | length 4.2
  Top Signal w0.305: U13.22@-20.966,20.189 -20.966,21.477 v1(-20.954,21.488)
  Bottom Signal w0.305: R34.1@-22.492,22.428 R36.1@-20.719,22.428 ; v1(-20.954,21.488) -20.719,21.723 R36.1@-20.719,22.428 ; R36.1@-20.663,22.428 R36.1@-20.719,22.428
NetR72_1: R72.1 U10.12 | length 6.4
  Top Signal w0.127: U10.12@-37.862,104.547 -37.862,103.924 -37.067,103.129 -37.067,99.717 -36.683,99.333 R72.1@-36.035,99.333
NetR107_1: R107.1 U23.5 | length 1.4
  Top Signal w0.203: U23.5@-43.552,12.764 -43.221,13.095 R107.1@-43.221,14.072
NetR172_2: R172.2 U2.3 | length 3.5
  Top Signal w0.2: R172.2@-25.892,136.878 -25.7,137.07 -25.16,137.07 -24.094,138.135 U2.3@-22.926,138.135
NetR173_2: R173.2 U2.4 | length 6.4
  Top Signal w0.2: R173.2@-27.931,137.037 -27.931,136.431 -27.653,136.153 -25.61,136.153 -24.028,137.735 U2.4@-22.926,137.735
NetR174_1: R174.1 R175.2 U2.70 | length 3.7
  Top Signal w0.152: U2.70@-7.526,128.535 -5.323,128.535 -5.223,128.435 -5.223,128.535 R175.2@-5.223,129.814
NetR176_2: R176.2 U2.59 | length 3.6
  Top Signal w0.152: R176.2@-13.1,123.143 -13.1,123.762 -12.768,124.094 -11.311,124.094 -11.026,124.379 U2.59@-11.026,125.035
NetS6_3: S6.3 U12.1 U12.2 | length 24
  Top Signal w0.203: S6.3@-44.623,59.84 -45.78,59.84 -46.177,59.442 -46.177,54.312 -44.748,52.883 -36.627,52.883 -35.966,52.222 -35.966,50.57 ; U12.1@-37.932,49.92 -36.288,49.92 -35.966,50.241 -35.966,50.57 ; U12.2@-37.932,50.57 -35.966,50.57
NetS6_6: S6.6 U12.6 U12.7 | length 15.6
  Top Signal w0.203: S6.6@-48.323,59.84 -47.14,59.84 -46.787,59.487 -46.787,53.162 -44.845,51.22 -44.183,51.22 ; U12.7@-42.382,50.57 -43.993,50.57 -44.183,50.76 -44.183,51.22 ; U12.6@-42.382,51.22 -44.183,51.22
QEP1_SEL: S5.5 U14.9 U14.10 U14.11 | length 11.9
  Top Signal w0.203: S5.5@-25.979,42.117 -25.533,42.117 -24.692,41.276 -24.692,35.422 ; U14.11@-23.652,34.122 -24.616,34.122 -24.692,34.198 -24.692,34.772 ; U14.10@-23.652,34.772 -24.692,34.772 ; U14.9@-23.652,35.422 -24.692,35.422 ; -24.692,34.772 -24.692,35.422
QEP2_SEL: S5.2 U11.9 U11.10 U11.11 | length 14
  Top Signal w0.203: U11.11@-32.669,34.091 -31.644,34.091 -31.14,34.595 -31.14,34.772 ; U11.10@-32.669,34.741 -31.171,34.741 -31.14,34.772 ; U11.9@-32.669,35.391 -31.14,35.391 ; S5.2@-30.124,41.961 -29.835,41.961 S5.2@-29.679,42.117 -30.629,42.117 -31.14,41.605 -31.14,35.391 ; -31.14,34.772 -31.14,35.391
UART_SEL1: S2.2 U6.1 U6.5 U9.1 U9.5 | length 16.1
  Top Signal w0.305: U6.1@-32.064,106.131 -32.064,106.882 -31.546,107.4 -29.947,107.4 ; S2.2@-28.444,102.133 -28.829,102.133 -30.048,103.353 -30.048,107.299 -29.947,107.4 ; U9.5@-26.534,106.106 -26.534,105.013 -26.695,104.851 -28.397,104.851 -28.534,104.988 U9.1@-28.534,106.106 -28.534,107.045 -28.889,107.4 -29.947,107.4
UART_SEL2: S2.5 U8.1 U8.5 | length 11.4
  Top Signal w0.305: S2.5@-24.744,102.133 -23.393,102.133 -21.692,103.835 -21.692,106.183 ; U8.5@-23.536,106.183 -21.692,106.183 ; U8.1@-23.536,108.183 -22.336,108.183 -21.692,107.538 -21.692,106.183
USB_CC1: R78.2 U16.4 U16.7 USB1.A5 | length 8.1
  Top Signal w0.152: R78.2@-48.241,130.865 -48.241,131.831 -47.787,132.285 -46.026,132.285 -45.088,133.223 U16.4@-45.088,133.899 U16.7@-45.088,134.734 -45.088,135.531 -45.555,135.998 -45.555,136.377 USB1.A5@-45.563,136.385
USB_CC2: R81.2 U16.5 U16.6 USB1.B5 | length 15.2
  Top Signal w0.152: R81.2@-46.756,130.981 -46.756,131.564 -46.303,132.017 -45.845,132.017 -44.588,133.274 -44.588,134.917 -44.564,134.941 -44.561,134.941 -44.454,135.048 v1(-44.039,135.048)
  Top Signal w0.305: v4@-46.836,137.41 USB1.B5@-46.836,138.185
  Middle Signal w0.305: v4(-46.828,137.402) -47.694,137.402 -48.783,136.313 -48.783,135.16 -48.282,134.659 -44.469,134.659 -44.08,135.048 v1(-44.039,135.048)
USB_D_N: U2.93 U16.1 U16.10 USB1.A7 USB1.B7 | length 52.5
  Top Signal w0.27: v1(-46.633,133.134) -46.588,133.18 U16.1@-46.588,133.899 -46.588,135.538 v1(-46.633,135.583) -46.586,135.63 USB1.A7@-46.586,136.585 ; USB1.B7@-45.836,138.185 -45.836,137.686 -45.609,137.459 v4(-45.609,137.424) ; v1(-12.145,135.335) -12.084,135.397 -12.084,136.001 -10.35,137.735 U2.93@-7.526,137.735
  Middle Signal w0.27: v1(-46.633,133.134) -46.466,132.967 -46.466,131.842 -43.136,128.513 -24.025,128.513 -17.837,134.7 -13.151,134.7 -12.544,135.306 -12.174,135.306 v1(-12.145,135.335)
  Bottom Signal w0.27: v1(-46.633,135.583) -45.609,136.608 v4(-45.609,137.424)
USB_D_P: U2.94 U16.2 U16.9 USB1.A6 USB1.B6 | length 50.2
  Top Signal w0.27: USB1.B6@-46.336,138.185 -46.336,137.418 -46.086,137.168 USB1.A6@-46.086,136.585 -46.086,134.246 -46.088,134.244 -46.088,133.901 -46.086,133.899 -46.086,133.339 v1(-45.876,133.129) ; v1(-12.626,136.056) -10.547,138.135 U2.94@-7.526,138.135
  Middle Signal w0.27: v1(-45.876,133.129) -46.043,132.961 -46.043,132.017 -42.961,128.935 -24.2,128.935 -18.136,134.999 -18.012,135.122 -13.326,135.122 -12.681,135.767 -12.681,136.001 v1(-12.626,136.056)
USB_GND: C80.1 C126.2 C127.2 C128.2 C129.2 C131.1 C132.2 C134.1 C135.1 C136.1 C137.1 C138.1 C139.2 C140.2 C141.1 C142.2 C143.1 C144.2 C145.1 C146.2 C147.2 JP1.3 LED1.1 LED7.1 LED8.2 LED9.2 R68.1 R78.1 R81.1 R175.1 R176.1 U2.10 U2.17 U2.48 U2.55 U2.58 U2.64 U2.66 U2.80 U2.114 U16.3@-45.588,133.899 U16.8@-45.588,134.734 U25.2 U25.4 U26.2 U26.8 U27.2 U27.8 USB1.1 USB1.2 USB1.3 USB1.4 USB1.A1 USB1.A12 USB1.B1 USB1.B12 Y1.2 Y1.4 | length 8.5
  Top Signal w0.2: v1(-24.248,132.566) -24.216,132.535 U2.17@-22.926,132.535 ; U2.114@-15.826,140.435 v1(-15.826,141.625) ; U2.48@-15.426,125.035 -15.426,125.826 v1(-15.062,126.19) ; v1(-8.602,126.935) U2.66@-7.526,126.935
  Top Signal w0.3: U16.8@-45.588,134.813 -45.567,134.834 U16.8@-45.583,134.85 ; U16.3@-45.583,133.961 v1@-45.583,135.271
  Top Signal w0.381: U2.55@-12.626,125.035 v1(-12.626,126.19) ; U2.58@-11.426,125.035 v1(-11.426,126.111)
  other v1: -49.633,121.81 -14.199,121.908 -15.561,122.762 -40.792,123.019 -2.454,123.407 -46.03,123.495 -15.086,123.704 -8.493,124.158 -47.836,124.924 -50.994,125.937 -7.242,126.002 -9.026,126.111 -49.804,127.089 -1.984,127.485 -32.223,127.557 -26.013,127.557 -18.221,127.557 -51.73,127.818 -53.261,127.877 -44.568,128.334 -48.241,128.445 -11.915,128.497 -19.941,128.544 -56.646,128.625 -49.571,129.278 -54.355,129.363 -45.622,129.392 -40.478,129.477 -34.56,129.755 -15.086,129.755 -10.061,129.755 -37.545,130.125 -29.286,130.125 -38.637,130.403 -12.231,130.735 -14.324,130.882 -49.629,130.912 -19.831,131.057 -2.817,131.099 -56.519,131.187 -4.05,131.224 -39.123,131.859 -17.026,131.859 -6.051,132.496 -54.532,132.546 -5.276,132.566 -3.834,132.831 -9.77,132.925 -2.076,132.925 -50.794,133.459 -12.001,133.829 -29.234,133.888 -9.77,134.126 -38.006,134.7 -50.909,134.734 -19.339,134.829 -45.574,135.381 -42.315,135.554 -43.586,135.71 -10.567,135.735 -49.867,135.759 -24.653,135.904 -39.524,136.053 -18.904,136.073 -17.553,136.121 -13.758,136.28 -31.126,136.482 -16.112,136.728 -14.977,136.93 -34.276,137.574 -6.258,137.599 -38.893,137.804 -2.234,138.224 -11.715,138.272 -24.656,138.535 -56.519,138.859 -21.058,138.877 -3.56,139.024 -13.398,139.17 -1.709,139.207 -30.839,139.24 -24.774,141.792 -34.56,141.812 -26.922,141.809 -29.286,141.914 -9.796,142.487 -53.617,142.606 -21.753,142.717 -14.718,142.873 -4.997,142.954
VDD: C54.1 C55.1 C56.1 C57.1 C58.1 C63.1 C74.2 C75.2 C103.1 C104.1 C105.1 C106.1 JP4.1 L1.2 TP1.1 U1.6 U1.8 U1.67 U1.71 U1.87 U1.98 U1.112 U1.123 U1.137 | length 80.8
  Top Signal w0.203: v3(-32.715,76.124) -32.706,76.124 U1.8@-31.926,75.343 ; v3(-32.258,76.81) -32.258,76.807 U1.6@-31.36,75.909 ; v3(-32.131,55.753) -32.131,55.763 U1.67@-31.36,56.534 ; v3(-30.963,54.661) -30.963,54.669 U1.71@-30.228,55.403 ; U1.137@-25.562,75.343 -24.527,76.378 v3(-24.501,76.378) ; U1.87@-23.582,59.08 -22.846,58.344 v3(-22.835,58.344) ; U1.123@-21.602,71.383 v3(-20.753,72.232) ; U1.98@-20.47,62.191 -19.736,61.456 v3(-19.736,61.413) ; U1.112@-18.49,68.272 -17.751,69.012 v3(-17.729,69.012)
  PWR w0.203: -35.865,94.183 -34.163,92.481 ; -33.835,75.682 -33.138,75.682 -32.715,76.105 v3(-32.715,76.124) -32.715,76.352 v3(-32.258,76.81) -31.979,77.089 -28.677,77.089 -27.965,76.378 v3(-24.501,76.378) -25.197,75.682 -25.197,75.235 -22.194,72.232 v3(-20.753,72.232) -20.753,70.111 -19.375,68.732 -18.009,68.732 ; v3(-32.131,55.753) -31.953,55.753 -31.42,55.22 -31.42,55.118 v3(-30.963,54.661) -30.099,55.524 -26.772,55.524 -24.206,58.09 -23.089,58.09 v3(-22.835,58.344) -22.758,58.42 -22.758,60.09 -21.435,61.413 v3(-19.736,61.413) -19.558,61.591 -19.558,62.789 -18.39,63.957 -18.39,68.351 -18.009,68.732 ; v3(-17.729,69.012) -18.009,68.732
  Bottom Signal w0.203: -35.865,94.183 -35.738,94.31 L1.2@-35.738,97.409 ; v3(-32.715,76.124) -31.971,75.38 C103.1@-31.971,75.151 ; v3(-32.258,76.81) -32.258,76.784 -31.445,75.971 -31.238,75.971 C63.1@-31.2,75.933 ; C56.1@-32.174,57.031 -32.131,56.987 v3(-32.131,55.753) ; v3(-30.963,54.661) -30.963,54.94 -30.498,55.405 C57.1@-30.472,55.405 ; C58.1@-25.551,75.349 -24.522,76.378 v3(-24.501,76.378) ; C106.1@-23.417,58.939 -23.417,58.901 -23.392,58.901 v3(-22.835,58.344) ; C55.1@-21.75,72.23 -21.748,72.232 v3(-20.753,72.232) ; C105.1@-20.365,62.008 -20.331,62.008 v3(-19.736,61.413) ; C104.1@-18.194,68.649 -17.831,69.012 v3(-17.729,69.012)
  Bottom Signal w0.381: v1(-34.036,57.302) -34.163,57.429 -34.163,58.395 C54.1@-33.89,58.667 ; C74.2@-11.547,71.425 -9.944,71.425 C75.2@-9.83,71.539 ; C75.2@-9.708,71.247 -9.708,71.271 -9.545,71.433 -9.051,71.433 v1(-9.017,71.399) v1(-8.204,71.399) ; v1@-8.204,71.413 -6.614,71.413 JP4.1@-6.341,71.14
  other v1: -35.433,93.904 -36.195,93.929 -36.195,94.539 -35.435,94.539
VDD_1P8: C89.1 R18.2 TP9.1 U10.3 | length 6.7
  Top Signal w0.254: C89.1@-41.859,106.251 -41.859,104.8 TP9.1@-42.367,104.292 -42.222,104.147 v1(-40.615,104.147) ; C89.1@-41.807,106.183 -41.807,106.415 -41.525,106.697 U10.3@-40.512,106.697
  Bottom Signal w0.254: v1(-40.615,104.147) R18.2@-39.506,104.147
VDDA: C51.1 C53.1 C61.1 C62.1 L2.2 TP3.1 U1.19 U1.54 U3.2 U12.8 | length 16.7
  Top Signal w0.203: v3(-35.966,59.284) -35.964,59.284 U1.54@-35.037,60.211 ; v3(-35.966,73.127) -35.932,73.127 U1.19@-35.037,72.232
  Top Signal w0.381: U12.8@-42.382,49.92 -41.208,49.92 v1(-41.173,49.886) ; U3.2@-38.225,45.593 v1(-36.178,45.593)
  PWR w0.203: -38.786,68.697 -35.966,71.517 v3(-35.966,73.127)
  Bottom Signal w0.203: v3(-35.966,59.284) -35.966,59.43 C61.1@-35.456,59.941 ; v3(-35.966,73.127) -35.769,73.127 C62.1@-35.199,72.557
  Bottom Signal w0.381: C51.1@-38.087,47.015 -38.087,45.593 v1(-36.178,45.593)
  other v1: -34.925,46.584 -33.96,46.584
VDDIO: C65.1 C66.1 C67.1 C68.1 C69.1 C70.1 C71.1 C72.1 C73.1 C97.1 C98.1 C99.1 C100.1 C101.1 C102.1 L3.2 TP2.1 U1.3 U1.9 U1.66 U1.68 U1.72 U1.81 U1.83 U1.95 U1.99 U1.106 U1.113 U1.118 U1.122 U1.136 | length 106.5
  Top Signal w0.203: v3(-33.249,76.459) -33.249,76.1 U1.9@-32.208,75.06 ; v3(-32.791,55.651) -32.791,55.668 U1.66@-31.643,56.817 ; v3(-32.182,55.118) -32.182,55.146 U1.68@-31.077,56.251 ; v3(-31.344,77.546) -31.3,77.546 U1.3@-30.511,76.757 ; v3(-30.404,54.153) -30.48,54.229 -30.48,54.585 U1.72@-29.946,55.12 ; U1.81@-25.279,57.383 -24.411,56.515 v3(-24.409,56.515) ; U1.136@-25.279,75.06 -24.647,75.692 v3(-24.587,75.692) ; U1.83@-24.713,57.948 -23.937,57.172 v3(-23.937,57.168) ; U1.95@-21.319,61.342 -20.599,60.623 v3(-20.599,60.604) ; U1.122@-21.319,71.1 -20.041,72.379 v3(-20.041,72.403) ; U1.99@-20.188,62.474 v3@-19.056,61.342 ; U1.118@-20.188,69.969 -19.329,70.827 v3(-19.329,70.841) ; U1.113@-18.773,68.555 -17.729,69.599 v3(-17.729,69.979) ; U1.106@-18.208,64.454 -17.475,63.721 v3(-17.475,63.703)
  PWR w0.203: v1@-43.763,106.097 v1(-43.79,106.07) -43.572,105.853 -43.572,105.653 v1(-43.739,105.486) -43.572,105.319 -43.572,98.745 -43.917,98.401 -42.62,97.104 ; v3(-33.249,76.459) -33.249,76.652 ; v3(-32.791,55.651) -32.258,55.118 v3(-32.182,55.118) -32.182,54.305 -31.547,53.67 -30.886,53.67 v3(-30.404,54.153) -30.251,54.305 -29.196,54.305 -28.975,54.084 -28.581,54.084 -28.36,54.305 v1(-26.314,54.305) -26.162,54.153 -25.883,54.153 -24.409,55.626 v3(-24.409,56.515) -24.409,56.695 v3(-23.937,57.168) -23.878,57.226 -22.803,57.226 -21.361,58.668 -21.361,59.944 -20.701,60.604 v3(-20.599,60.604) -20.44,60.445 -20.44,60.039 -20.168,59.766 -19.533,59.766 -19.304,59.995 -19.304,60.02 -19.177,60.147 -19.177,61.228 -17.475,62.93 v3(-17.475,63.703) -17.475,66.852 -16.408,67.918 -16.408,68.732 -16.332,68.809 -16.332,69.723 -16.561,69.952 -16.662,69.85 -17.678,69.85 -17.729,69.901 v3(-17.729,69.979) -17.729,71.044 -18.632,71.947 ; -32.355,77.546 v3(-31.344,77.546) -29.71,77.546 -28.999,78.257 -25.359,78.257 -23.652,76.55 ; v3(-19.329,70.841) -19.329,71.349 -18.731,71.947 -18.632,71.947 ; -23.652,76.55 -23.581,76.479 -20.041,72.939 v3(-20.041,72.403) -19.089,72.403 -18.632,71.947 ; -23.652,76.55 -23.652,76.408 -24.369,75.692 v3(-24.587,75.692) -23.729,76.55 -23.652,76.55
  Bottom Signal w0.203: v3(-33.249,76.459) -33.249,74.887 C99.1@-32.758,74.397 ; C71.1@-32.987,57.843 -33.045,57.785 -33.045,55.905 v3(-32.791,55.651) ; v3(-32.182,55.118) -32.182,55.143 -31.311,56.015 C66.1@-31.311,56.218 ; v3(-31.344,77.546) -31.293,77.546 -30.454,76.707 C100.1@-30.422,76.707 ; v3(-30.404,54.153) -30.15,54.153 C72.1@-29.685,54.618 ; C98.1@-25.281,57.158 -25.042,57.158 -24.409,56.524 v3(-24.409,56.515) ; C69.1@-24.773,74.592 -24.773,75.548 -24.628,75.692 v3(-24.587,75.692) ; C97.1@-24.468,57.97 -24.468,57.698 v3(-23.937,57.168) ; C102.1@-21.182,61.189 v3(-20.599,60.604) v3(-20.599,60.604) ; C67.1@-20.988,71.417 -20.988,71.456 v3(-20.041,72.403) ; C70.1@-20.213,70.637 -20.009,70.841 v3(-19.329,70.841) ; C101.1@-19.591,62.796 -19.056,62.262 -19.056,61.373 v3(-19.025,61.341) ; C68.1@-19.413,69.881 -19.241,70.053 -17.803,70.053 v3(-17.729,69.979) ; C73.1@-18.067,64.193 -17.965,64.193 v3(-17.475,63.703) ; v1(-44.526,105.994) -44.526,106.071 v1(-44.526,105.994)
  Bottom Signal w0.381: v1(-26.314,54.305) -26.314,55.511 C65.1@-25.876,55.949
  other v1: -44.526,105.419
VREFHIAB: C13.1 S6.5 U1.30 | length 24.5
  Top Signal w0.127: C13.1@-50.724,57.847 C13.1@-50.724,58.076 ; S6.5@-48.323,58.09 -50.71,58.09 C13.1@-50.724,58.076 ; U1.30@-38.148,69.121 -39.538,70.51 -40.161,70.51 -41.897,68.774 -41.897,67.135 -43.942,65.091 -43.942,62.332 -44.755,61.519 -48.971,61.519 -50.724,59.766 C13.1@-50.724,58.076
VREFHICDE: C14.1 S6.2 U1.46 | length 10.6
  Top Signal w0.127: S6.2@-44.623,58.09 -44.585,58.052 -42.469,58.052 -39.281,58.052 -38.659,58.674 -38.659,61.115 U1.46@-37.3,62.474
VREG: C90.1 TP10.1 U10.10 U10.11 | length 15.9
  Top Signal w0.203: TP10.1@-38.862,99.101 -38.862,99.822 -38.862,100.838 ; U10.10@-38.862,104.547 -38.862,103.937 ; TP10.1@-38.702,98.941 -38.702,99.662 C90.1@-38.702,100.678 ; -38.532,99.333 -38.532,99.624 ; C90.1@-38.532,100.824 -38.532,100.508 ; TP10.1@-38.362,98.73 -38.362,99.503 -38.362,99.793 ; U10.11@-38.362,104.547 -38.362,103.911 ; -38.862,100.838 -38.862,103.937 ; -38.862,100.838 C90.1@-38.702,100.678 ; -38.862,103.937 -38.387,103.937 -38.362,103.911 ; C90.1@-38.702,100.678 -38.532,100.508 ; -38.532,99.624 -38.362,99.793 ; -38.532,99.624 -38.532,100.508 ; -38.532,100.508 -38.362,100.678 ; -38.362,99.793 -38.362,100.678 ; -38.362,100.678 -38.362,103.911
XDS_RESET_INT: J101.10 U5.1 U27.14 | length 19
  Top Signal w0.127: U27.14@-28.529,115.118 v1(-28.529,113.919) -28.473,113.919 -27.897,113.343 -26.581,113.343 -26.134,112.896 -26.134,111.935 -25.669,111.47 -25.606,111.47 U5.1@-25.494,111.358 ; J101.10@-20.604,111.903 -20.604,110.056 v1(-20.581,110.033)
  Middle Signal w0.127: v1(-28.529,113.919) -28.148,113.538 -21.107,113.538 -20.853,113.284 -20.853,110.306 v1(-20.581,110.033)
XDS_RESET_OUT: R16.1 U2.40 U27.3 | length 13.7
  Top Signal w0.152: v1(-18.76,123.867) -18.143,123.25 R16.1@-17.53,123.25 ; v1@-18.626,124 U2.40@-18.626,125.035
  Top Signal w0.2: v1(-28.529,123.734) U27.3@-28.529,124.868
  Middle Signal w0.152: v1(-28.529,123.734) -18.893,123.734 v1(-18.76,123.867) v1@-18.626,124
XDS_RXD: U2.33 U27.5 | length 12.8
  Top Signal w0.152: U27.5@-31.069,124.868 -31.069,125.904 -30.628,126.344 -24.623,126.344 -22.279,124 -21.571,124 -21.426,124.145 U2.33@-21.426,125.035
XDS_TCK_SWDCLK: U2.35 U26.4 | length 22.7
  Top Signal w0.152: U2.35@-20.626,125.035 v1(-20.626,126.002)
  Top Signal w0.2: U26.4@-40.916,124.868 v1(-40.916,126.196)
  Middle Signal w0.152: v1(-40.916,126.196) -20.93,126.196 -20.736,126.002 v1(-20.626,126.002)
XDS_TDI: U2.38 U26.5 | length 25.3
  Top Signal w0.152: v1(-20.628,126.802) -20.581,126.754 -20.433,126.754 -19.426,125.747 U2.38@-19.426,125.035
  Top Signal w0.2: U26.5@-42.186,124.868 -42.093,124.961 -42.093,126.049 v1(-41.382,126.76)
  Middle Signal w0.152: v1(-41.382,126.76) -20.671,126.76 v1(-20.628,126.802)
XDS_TDO_SWO: U2.37 U26.6 | length 27.2
  Top Signal w0.152: U26.6@-43.456,124.868 -43.456,123.943 -41.611,122.098 -21.572,122.098 -19.826,123.844 U2.37@-19.826,125.035
XDS_TMS_SWDIO: U2.36 U26.3 | length 22.8
  Top Signal w0.152: U26.3@-39.646,124.868 -39.646,123.943 -38.146,122.443 -21.594,122.443 -20.226,123.81 U2.36@-20.226,125.035
XDS_TXD: U2.34 U27.4 | length 12
  Top Signal w0.152: U27.4@-29.799,124.868 -29.79,124.877 -29.79,125.876 -29.624,126.043 -24.898,126.043 -22.486,123.631 -21.518,123.631 -21.45,123.699 -21.446,123.699 -21.026,124.119 U2.34@-21.026,125.035
XRSn: C28.1 J4/J2.16 J8/J6.56 R59.1 S1.4 U1.103 U10.6 | length 151.4
  Top Signal w0.127: v1(-41.3,105.283) -41.237,105.219 -40.534,105.219 U10.6@-40.512,105.197 ; U1.103@-19.056,63.605 -18.037,62.586 -15.342,62.586 v1(-15.316,62.611) ; J8/J6.56@-6.341,33.04 -5.436,33.04 -4.851,33.624 -4.851,44.073 -7.112,46.333 -7.112,47.955 -6.883,48.184 -5.791,48.184 -4.14,49.835 -4.14,62.457 -5.556,63.873 -5.556,64.103 v1(-5.639,64.186) ; v1@-4.089,115.404 S1.4@-2.977,115.404
  Middle Signal w0.127: v1(-41.3,105.283) -41.3,109.195 -40.386,110.109 -37.097,110.109 -36.741,110.465 -26.34,110.465 -24.663,108.788 -11.913,108.788 -5.309,115.392 v1(-4.089,115.392)
  Bottom Signal w0.127: v1(-15.316,62.611) -15.179,62.474 -10.967,62.474 -9.22,64.221 -7.747,64.221 R59.1@-7.696,64.272 -7.645,64.221 -6.401,64.221 C28.1@-6.35,64.272 ; C28.1@-6.35,64.221 -6.315,64.186 v1(-5.639,64.186) -5.639,64.262 -3.759,66.142 -3.759,93.958 J4/J2.16@-6.341,96.54 -4.801,98.08 -4.801,114.681 v1(-4.089,115.392)
XTAL_X1: C19.1 R21.2 R22.2 | length 2.8
  Top Signal w0.203: R21.2@-16.052,61.747 -16.052,60.292 -14.826,60.291 C19.1@-14.757,60.36
XTAL_X2: C20.1 R20.2 Y2.1 | length 5.2
  Top Signal w0.203: R20.2@-18.665,58.691 -18.657,58.684 C20.1@-17.323,58.684 -17.069,58.43 -17.069,56.51 Y2.1@-18.169,55.41
pads on no net: FID1.1 FID2.1 FID3.1 FID4.1 FID5.1 FID6.1 J11.9 J101.7 M1.0 M2.0 M3.0 M4.0 M6.0 M7.0 MH1.1 MH2.1 MH3.1 MH4.1 S1. S6.1 S6.4 U1.2 U1.12 U1.13 U1.15 U1.16 U1.21 U1.33 U1.34 U1.39 U1.47 U1.48 U1.49 U1.50 U1.51 U1.52 U1.56 U1.57 U1.59 U1.60 U1.61 U1.62 U2.1 U2.2 U2.5 U2.6 U2.11 U2.12 U2.13 U2.14 U2.15 U2.18 U2.19 U2.20 U2.21 U2.22 U2.23 U2.24 U2.25 U2.27 U2.29 U2.30 U2.31 U2.32 U2.41 U2.42 U2.43 U2.44 U2.45 U2.46 U2.49 U2.50 U2.53 U2.54 U2.56 U2.57 U2.65 U2.67 U2.71 U2.72 U2.73 U2.74 U2.75 U2.76 U2.77 U2.78 U2.81 U2.82 U2.83 U2.84 U2.85 U2.86 U2.91 U2.92 U2.95 U2.97 U2.98 U2.99 U2.100 U2.102 U2.103 U2.104 U2.105 U2.106 U2.107 U2.108 U2.109 U2.110 U2.111 U2.112 U2.116 U2.117 U2.118 U2.119 U2.120 U2.121 U2.123 U2.124 U2.125 U2.126 U2.127 U2.128 U3.1 U3.3 U3.7 U3.8 U5.2 U10.5 U10.7 U10.8 U10.17 U10.20 U15.5 U15.8 U16.3@-45.588,133.899 U16.8@-45.588,134.734 U23.4 U27.6 U27.11 USB1.A2 USB1.A3 USB1.A8 USB1.A10 USB1.A11 USB1.B2 USB1.B3 USB1.B8 USB1.B10 USB1.B11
